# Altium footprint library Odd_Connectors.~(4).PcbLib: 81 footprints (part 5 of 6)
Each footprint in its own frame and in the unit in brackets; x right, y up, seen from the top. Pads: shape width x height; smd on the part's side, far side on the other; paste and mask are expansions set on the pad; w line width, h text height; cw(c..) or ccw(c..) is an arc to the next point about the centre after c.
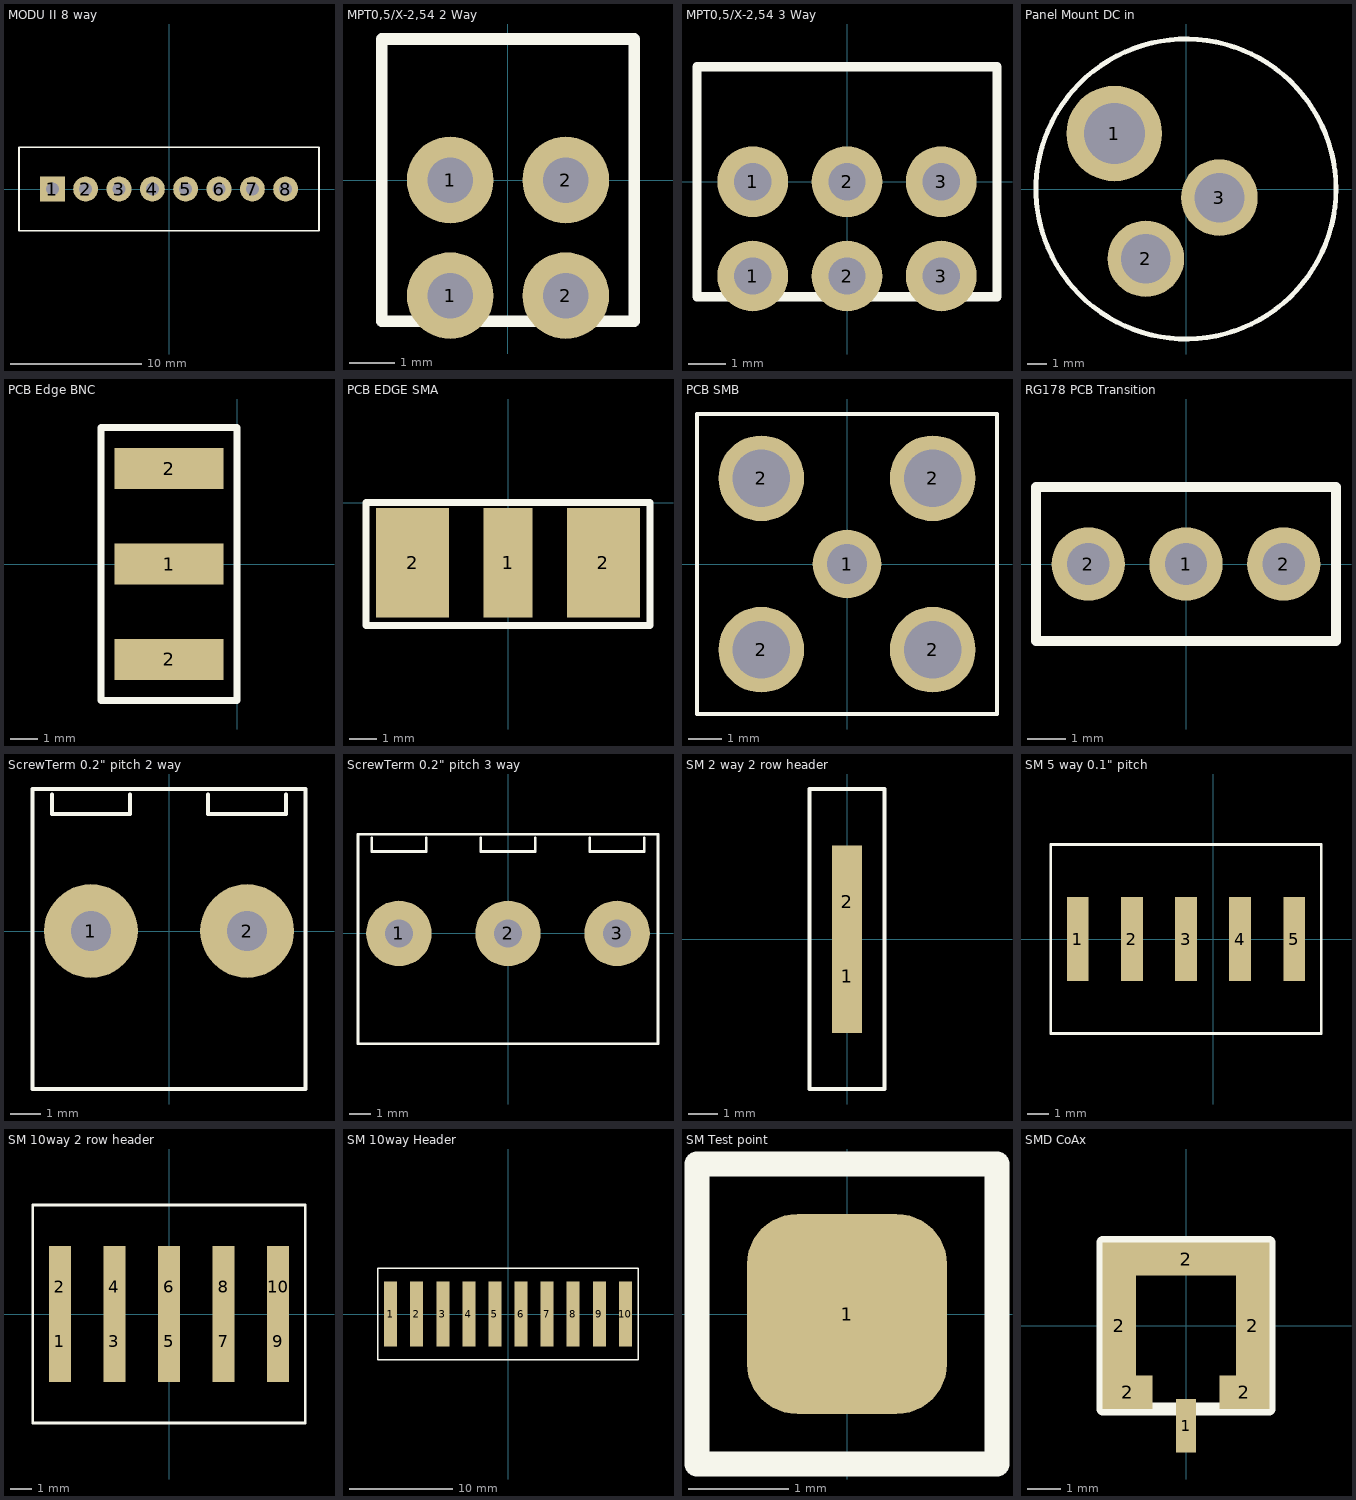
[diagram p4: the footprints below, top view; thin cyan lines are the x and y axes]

## MODU II 8 way [mm] "Amp Modu ii headers"
height 15
pads (8):
  rect 1.905x1.905 hole 1: 1(-8.89,0)
  round 1.905 hole 1: 2(-6.35,0) 3(-3.81,0) 4(-1.27,0) 5(1.27,0) 6(3.81,0) 7(6.35,0) 8(8.89,0)
Top Overlay:
  lines w0.127: -11.43,-3.175 11.43,-3.175 11.43,3.175 -11.43,3.175 -11.43,-3.175

## MPT0,5/X-2,54 2 Way [mm] "0.1\" pitch screw terminals"
height 5.08
pads (4):
  round 1.905 hole 1: 1(-1.27,-2.54) 1(-1.27,0) 2(1.27,-2.54) 2(1.27,0)
Top Overlay:
  lines w0.254: -2.77,-3.1 2.77,-3.1 2.77,3.1 -2.77,3.1 -2.77,-3.1

## MPT0,5/X-2,54 3 Way [mm] "0.1\" pitch screw terminals"
height 5.08
pads (6):
  round 1.905 hole 1: 1(-2.54,-2.54) 1(-2.54,0) 2(0,-2.54) 2(0,0) 3(2.54,-2.54) 3(2.54,0)
Top Overlay:
  lines w0.254: -4.04,-3.1 -4.04,3.1 4.04,3.1 4.04,-3.1 -4.04,-3.1

## Panel Mount DC in [mm] "Panel Mount DC in mounted horiz on PCB"
pads (3):
  round 5 hole 3.2: 1(-3.75,2.9)
  round 4 hole 2.6: 2(-2.1,-3.65) 3(1.75,-0.45)
Top Overlay:
  circle w0.254: c0,0 r7.85

## PCB Edge BNC [mm]
pads (3):
  rect 4x1.5 smd: 1(-2.5,0) 2(-2.5,-3.5) 2(-2.5,3.5)
Top Overlay:
  lines w0.254: -5,-5 -5,5 0,5 0,-5 -5,-5

## PCB EDGE SMA [mm] "Edge launch SMA such as Molex 73251-2120"
pads (3):
  rect 1.78x4 smd: 1(0,-2.2)
  rect 2.665x4 smd: 2(-3.492,-2.2) 2(3.492,-2.2)
Top Overlay:
  lines w0.254: -5.2,-4.5 5.2,-4.5 5.2,0 -5.2,0 -5.2,-4.5

## PCB SMB [mm] "PCB mount SMB connector"
height 15
pads (5):
  round 2.032 hole 1.2: 1(0,0)
  round 2.54 hole 1.7: 2(-2.54,-2.54) 2(-2.54,2.54) 2(2.54,-2.54) 2(2.54,2.54)
Top Overlay:
  lines w0.127: -4.445,-4.445 4.445,-4.445 4.445,4.445 -4.445,4.445 -4.445,-4.445

## RG178 PCB Transition [mm] "Connect coax to pcb"
height 10
pads (3):
  round 1.905 hole 1.1: 1(0,0) 2(-2.54,0) 2(2.54,0)
Top Overlay:
  lines w0.254: -3.9,-2 -3.9,2 3.9,2 3.9,-2 -3.9,-2

## ScrewTerm 0.2" pitch 2 way [mil] "PCB mounted screw terminal 0.2\" pitch  Camden"
height 551.18
pads (2):
  round 120 hole 51.18: 1(-100,0) 2(100,0)
Top Overlay:
  lines w5: -150,175 -150,150 -50,150 -50,175 ; 50,175 50,150 150,150 150,175 ; -175,-202.5 175,-202.5 175,182 -175,182 -175,-202.5

## ScrewTerm 0.2" pitch 3 way [mil] "PCB mounted screw terminal 0.2\" pitch  Camden"
height 551.18
pads (3):
  round 120 hole 51.18: 1(-200,0) 2(0,0) 3(200,0)
Top Overlay:
  lines w5: -250,175 -250,150 -150,150 -150,175 ; -50,175 -50,150 50,150 50,175 ; 150,175 150,150 250,150 250,175 ; -275,-202.5 275,-202.5 275,182 -275,182 -275,-202.5

## SM 2 way 2 row header [mil]
height 393.7
pads (2):
  rect 40x150 smd: 1(0,-50) 2(0,50)
Top Overlay:
  lines w5: -50,-200 -50,200 50,200 50,-200 -50,-200

## SM 5 way 0.1" pitch [mil]
height 393.7
pads (5):
  rect 40x155 smd: 1(-250,0) 2(-150,0) 3(-50,0) 4(50,0) 5(150,0)
Top Overlay:
  lines w5: -300,-175 200,-175 200,175 -300,175 -300,-175

## SM 10way 2 row header [mil]
height 393.7
pads (10):
  rect 40x150 smd: 1(-200,-50) 2(-200,50) 3(-100,-50) 4(-100,50) 5(0,-50) 6(0,50) 7(100,-50) 8(100,50) 9(200,-50) 10(200,50)
Top Overlay:
  lines w5: -250,-200 250,-200 250,200 -250,200 -250,-200

## SM 10way Header [mil] "SM 10 way header 0.1\" pitch"
height 401.57
pads (10):
  rect 50x250 smd: 1(-450,0) 2(-350,0) 3(-250,0) 4(-150,0) 5(-50,0) 6(50,0) 7(150,0) 8(250,0) 9(350,0) 10(450,0)
Top Overlay:
  lines w5: -500,-175 500,-175 500,175 -500,175 -500,-175

## SM Test point [mm] "SM Test point 100 x 100mil"
pads (1):
  rrect50% 2x2 smd: 1(0,0)
Top Overlay:
  lines w0.254: -1.5,-1.5 1.5,-1.5 1.5,1.5 -1.5,1.5 -1.5,-1.5

## SMD CoAx [mm] "MIL-STD-348 sm coax"
height 4.1
pads (6):
  rect 0.6x1.6 smd: 1(0,-3)
  rect 1x5 smd: 2(-2,0) 2(2,0)
  rect 1.5x1 smd: 2(-1.75,-2) 2(1.75,-2)
  rect 5x1 smd: 2(0,2)
Top Overlay:
  lines w0.381: -2.5,-2.5 2.5,-2.5 2.5,2.5 -2.5,2.5 -2.5,-2.5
